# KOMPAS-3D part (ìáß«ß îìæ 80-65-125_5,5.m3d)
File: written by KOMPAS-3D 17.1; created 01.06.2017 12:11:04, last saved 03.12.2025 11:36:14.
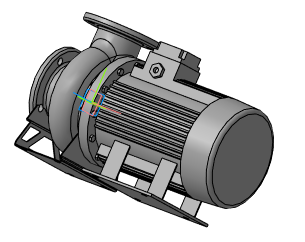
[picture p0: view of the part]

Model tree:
1. Операция без истории:6

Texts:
  ООО АДЛ ГРУПП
